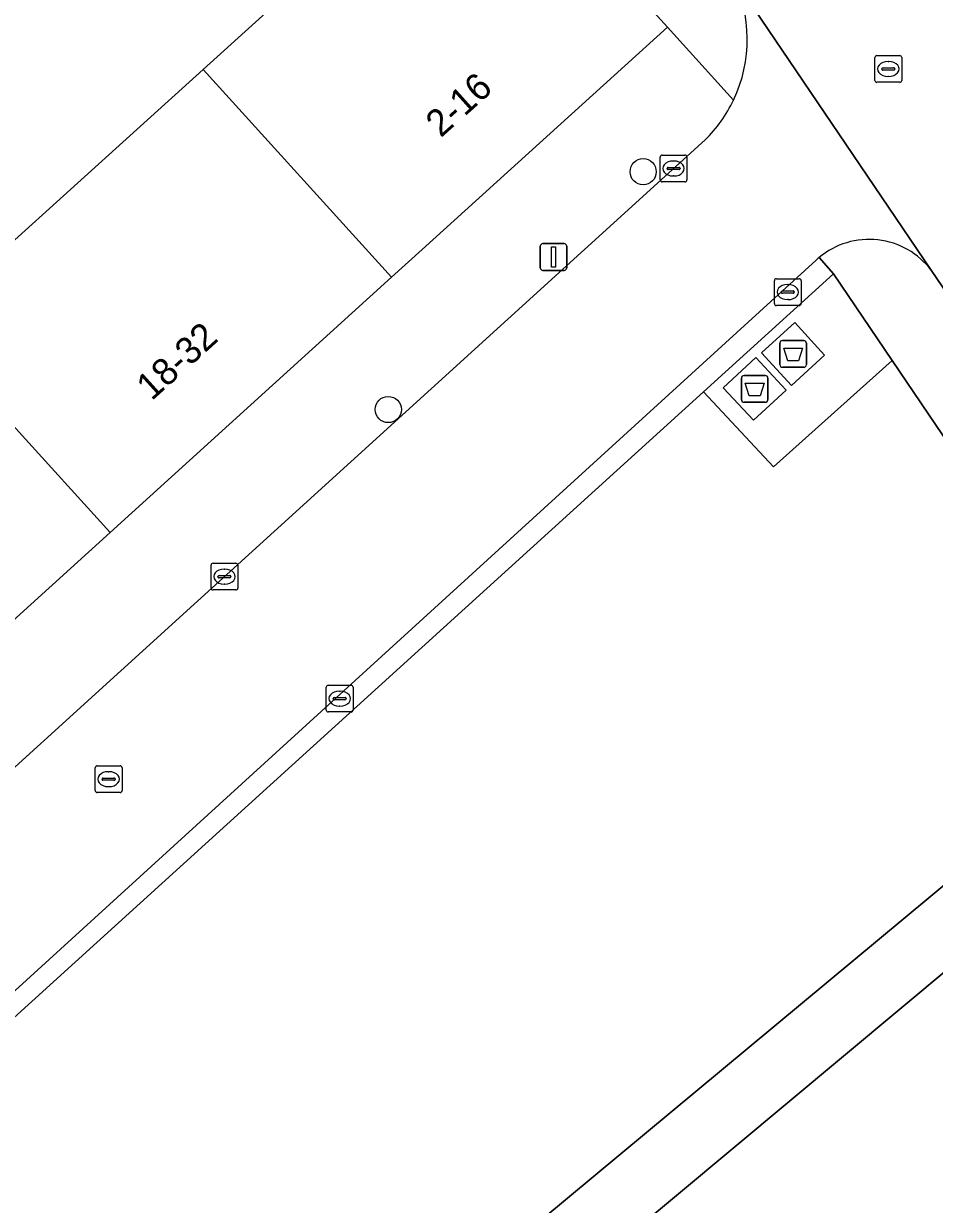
# Model space of a CAD drawing. Extents: x 159888 to 160761, y 384031 to 384750.
# Drawn here: x 160419.72 to 160453.75, y 384214.34 to 384258.44 of the extents above; entities that cross this region are included whole.
import ezdxf

# ---------------------------------------------------------------- set-up
doc = ezdxf.new("R2010")
doc.units = 0
for name, color, linetype in [('IMGEO_Afval_apart_plaats', 7, 'Continuous'), ('IMGEO_Boom', 7, 'Continuous'), ('IMGEO_Erf', 7, 'Continuous'), ('IMGEO_Groenvoorziening', 7, 'Continuous'), ('IMGEO_Kolk', 7, 'Continuous'), ('IMGEO_Lichtmast', 7, 'Continuous'), ('IMGEO_Pand', 7, 'Continuous'), ('IMGEO_Pand_nummerreeks', 7, 'Continuous'), ('IMGEO_Rijbaan_lokaal_open', 7, 'Continuous'), ('IMGEO_Rioolput', 7, 'Continuous'), ('IMGEO_Voetpad_gesloten', 7, 'Continuous'), ('IMGEO_Voetpad_open', 7, 'Continuous')]:
    doc.layers.add(name, color=color, linetype=linetype)

msp = doc.modelspace()

# ---------------------------------------------------------------- linework, layer by layer
at = {"layer": 'IMGEO_Afval_apart_plaats'}
for p, q in [((160447.976, 384245.698), (160447.976, 384246.498)), ((160447.976, 384246.498), (160447.976, 384245.698)), ((160448.076, 384246.598), (160448.866, 384246.598)), ((160448.866, 384246.598), (160448.076, 384246.598)), ((160448.966, 384246.498), (160448.966, 384245.698)), ((160448.966, 384245.698), (160448.966, 384246.498)), ((160448.866, 384245.598), (160448.076, 384245.598)), ((160448.076, 384245.598), (160448.866, 384245.598)), ((160446.54, 384244.392), (160446.54, 384245.192)), ((160446.54, 384245.192), (160446.54, 384244.392)), ((160446.64, 384245.292), (160447.43, 384245.292)), ((160447.43, 384245.292), (160446.64, 384245.292)), ((160447.53, 384245.192), (160447.53, 384244.392)), ((160447.53, 384244.392), (160447.53, 384245.192)), ((160447.43, 384244.292), (160446.64, 384244.292)), ((160446.64, 384244.292), (160447.43, 384244.292))]:
    msp.add_line(p, q, dxfattribs=at)
for points in [[(160448.119, 384246.312), (160448.823, 384246.312), (160448.674, 384245.842), (160448.268, 384245.842), (160448.119, 384246.312)], [(160446.683, 384245.006), (160447.387, 384245.006), (160447.238, 384244.536), (160446.832, 384244.536), (160446.683, 384245.006)]]:
    msp.add_lwpolyline(points, dxfattribs=at)
for centre, start, end in [((160448.076, 384246.498), 90, 180), ((160448.076, 384246.498), 90, 180), ((160448.866, 384246.498), 0, 90), ((160448.866, 384246.498), 360, 90), ((160448.076, 384245.698), 180, 270), ((160448.076, 384245.698), 180, 270), ((160448.866, 384245.698), 270, 0), ((160448.866, 384245.698), 270, 0), ((160446.64, 384245.192), 90, 180), ((160446.64, 384245.192), 90, 180), ((160447.43, 384245.192), 0, 90), ((160447.43, 384245.192), 360, 90), ((160446.64, 384244.392), 180, 270), ((160446.64, 384244.392), 180, 270), ((160447.43, 384244.392), 270, 0), ((160447.43, 384244.392), 270, 0)]:
    msp.add_arc(centre, 0.1, start, end, dxfattribs=at)
at = {"layer": 'IMGEO_Boom'}
for centre in [(160442.868, 384252.904), (160433.344, 384244.022)]:
    msp.add_circle(centre, 0.489, dxfattribs=at)
at = {"layer": 'IMGEO_Erf'}
for points in [[(160415.894, 384247.195), (160418.994, 384250), (160426.423, 384256.722), (160436.74, 384266.058), (160437.684, 384267.073), (160432.866, 384274.257), (160406.309, 384250), (160394.332, 384239.06), (160393.278, 384238.132), (160385.071, 384230.903), (160377.553, 384231.423), (160373.824, 384235.664), (160374.226, 384244.326), (160369.777, 384244.623), (160364.144, 384239.222), (160389.244, 384208.933), (160391.374, 384210.83), (160384.306, 384218.612), (160394.835, 384228.14), (160405.365, 384237.667)], [(160445.745, 384203.546), (160456.575, 384212.575), (160467.421, 384221.617), (160468.175, 384222.224), (160462.762, 384230.216), (160419.38, 384194.033), (160413.229, 384188.902), (160401.999, 384190.089), (160403.03, 384199.875), (160396.267, 384200.587), (160392.322, 384197.688), (160392.679, 384197.264), (160418.154, 384167.028), (160419.883, 384168.51), (160413.255, 384176.46), (160424.085, 384185.489), (160434.915, 384194.518)]]:
    msp.add_lwpolyline(points, close=True, dxfattribs=at)
at = {"layer": 'IMGEO_Groenvoorziening'}
msp.add_lwpolyline([(160419.212, 384221.179), (160417.064, 384200.601), (160419.671, 384197.644), (160461.362, 384232.282), (160452.167, 384245.857), (160447.736, 384241.886), (160445.123, 384244.678)], close=True, dxfattribs=at)
at = {"layer": 'IMGEO_Kolk'}
for p, q in [((160443.502, 384252.598), (160443.502, 384253.45)), ((160443.577, 384253.524), (160444.429, 384253.524)), ((160444.503, 384253.45), (160444.503, 384252.598)), ((160443.761, 384253.018), (160443.761, 384253.03)), ((160443.804, 384253.067), (160444.202, 384253.067)), ((160443.99, 384253.304), (160444.015, 384253.304)), ((160444.245, 384253.03), (160444.245, 384253.018)), ((160444.199, 384252.981), (160443.801, 384252.981)), ((160444.013, 384252.744), (160443.988, 384252.744)), ((160444.429, 384252.524), (160443.577, 384252.524)), ((160447.771, 384247.981), (160447.771, 384248.833)), ((160447.846, 384248.907), (160448.698, 384248.907)), ((160448.259, 384248.687), (160448.284, 384248.687)), ((160448.772, 384248.833), (160448.772, 384247.981)), ((160448.03, 384248.401), (160448.03, 384248.413)), ((160448.468, 384248.364), (160448.07, 384248.364)), ((160448.073, 384248.45), (160448.471, 384248.45)), ((160448.514, 384248.413), (160448.514, 384248.401)), ((160448.698, 384247.907), (160447.846, 384247.907)), ((160448.282, 384248.127), (160448.257, 384248.127)), ((160426.72, 384237.356), (160426.72, 384238.208)), ((160426.795, 384238.282), (160427.647, 384238.282)), ((160427.208, 384238.062), (160427.233, 384238.062)), ((160427.721, 384238.208), (160427.721, 384237.356)), ((160426.979, 384237.776), (160426.979, 384237.788)), ((160427.417, 384237.739), (160427.019, 384237.739)), ((160427.022, 384237.825), (160427.42, 384237.825)), ((160427.463, 384237.788), (160427.463, 384237.776)), ((160427.647, 384237.282), (160426.795, 384237.282)), ((160427.231, 384237.502), (160427.206, 384237.502)), ((160431.027, 384232.799), (160431.027, 384233.651)), ((160431.102, 384233.725), (160431.954, 384233.725)), ((160432.028, 384233.651), (160432.028, 384232.799)), ((160431.286, 384233.219), (160431.286, 384233.231)), ((160431.724, 384233.182), (160431.326, 384233.182)), ((160431.329, 384233.268), (160431.727, 384233.268)), ((160431.515, 384233.505), (160431.54, 384233.505)), ((160431.77, 384233.231), (160431.77, 384233.219)), ((160431.954, 384232.725), (160431.102, 384232.725)), ((160431.538, 384232.945), (160431.513, 384232.945))]:
    msp.add_line(p, q, dxfattribs=at)
for points in [[(160443.502, 384252.598), (160443.502, 384253.45)], [(160443.577, 384253.524), (160444.429, 384253.524)], [(160444.503, 384253.45), (160444.503, 384252.598)], [(160444.429, 384252.524), (160443.577, 384252.524)], [(160447.771, 384247.981), (160447.771, 384248.833)], [(160447.846, 384248.907), (160448.698, 384248.907)], [(160448.772, 384248.833), (160448.772, 384247.981)], [(160448.698, 384247.907), (160447.846, 384247.907)], [(160426.72, 384237.356), (160426.72, 384238.208)], [(160426.795, 384238.282), (160427.647, 384238.282)], [(160427.721, 384238.208), (160427.721, 384237.356)], [(160427.647, 384237.282), (160426.795, 384237.282)], [(160431.027, 384232.799), (160431.027, 384233.651)], [(160431.102, 384233.725), (160431.954, 384233.725)], [(160432.028, 384233.651), (160432.028, 384232.799)], [(160431.954, 384232.725), (160431.102, 384232.725)]]:
    msp.add_lwpolyline(points, dxfattribs=at)
for centre, radius, start, end in [((160443.579, 384253.448), 0.0765, 91.552, 178.448), ((160443.579, 384253.448), 0.0765, 91.552, 178.448), ((160444.427, 384253.448), 0.0765, 1.552, 88.448), ((160444.427, 384253.448), 0.0765, 1.552, 88.448), ((160443.801, 384253.027), 0.0403, 85.8775, 175.7526), ((160443.798, 384253.017), 0.0366, 178.938, 274.7102), ((160444.202, 384253.024), 0.043, 264.8664, 352.4533), ((160444.206, 384253.029), 0.0386, 1.7309, 96.639), ((160443.579, 384252.6), 0.0765, 181.552, 268.448), ((160443.579, 384252.6), 0.0765, 181.552, 268.448), ((160444.427, 384252.6), 0.0765, 271.552, 358.448), ((160444.427, 384252.6), 0.0765, 271.552, 358.448), ((160447.848, 384248.831), 0.0765, 91.552, 178.448), ((160447.848, 384248.831), 0.0765, 91.552, 178.448), ((160448.696, 384248.831), 0.0765, 1.552, 88.448), ((160448.696, 384248.831), 0.0765, 1.552, 88.448), ((160448.07, 384248.41), 0.0403, 85.8775, 175.7526), ((160448.067, 384248.4), 0.0366, 178.938, 274.7102), ((160448.471, 384248.407), 0.043, 264.8664, 352.4533), ((160448.475, 384248.412), 0.0386, 1.7309, 96.639), ((160447.848, 384247.983), 0.0765, 181.552, 268.448), ((160447.848, 384247.983), 0.0765, 181.552, 268.448), ((160448.696, 384247.983), 0.0765, 271.552, 358.448), ((160448.696, 384247.983), 0.0765, 271.552, 358.448), ((160426.797, 384238.206), 0.0765, 91.552, 178.448), ((160426.797, 384238.206), 0.0765, 91.552, 178.448), ((160427.645, 384238.206), 0.0765, 1.552, 88.448), ((160427.645, 384238.206), 0.0765, 1.552, 88.448), ((160427.019, 384237.785), 0.0403, 85.8775, 175.7526), ((160427.016, 384237.775), 0.0366, 178.938, 274.7102), ((160427.42, 384237.782), 0.043, 264.8664, 352.4533), ((160427.424, 384237.787), 0.0386, 1.7309, 96.639), ((160426.797, 384237.358), 0.0765, 181.552, 268.448), ((160426.797, 384237.358), 0.0765, 181.552, 268.448), ((160427.645, 384237.358), 0.0765, 271.552, 358.448), ((160427.645, 384237.358), 0.0765, 271.552, 358.448), ((160431.104, 384233.649), 0.0765, 91.552, 178.448), ((160431.104, 384233.649), 0.0765, 91.552, 178.448), ((160431.952, 384233.649), 0.0765, 1.552, 88.448), ((160431.952, 384233.649), 0.0765, 1.552, 88.448), ((160431.326, 384233.228), 0.0403, 85.8775, 175.7526), ((160431.323, 384233.218), 0.0366, 178.938, 274.7102), ((160431.727, 384233.225), 0.043, 264.8664, 352.4533), ((160431.731, 384233.23), 0.0386, 1.7309, 96.639), ((160431.104, 384232.801), 0.0765, 181.552, 268.448), ((160431.104, 384232.801), 0.0765, 181.552, 268.448), ((160431.952, 384232.801), 0.0765, 271.552, 358.448), ((160431.952, 384232.801), 0.0765, 271.552, 358.448)]:
    msp.add_arc(centre, radius, start, end, dxfattribs=at)
for centre, major_axis, ratio, start_param, end_param in [((160443.989, 384253.024), (-0.387, 0.002), 0.722429, 4.712389, 7.853982), ((160444.014, 384253.024), (-0.39, 0.002), 0.717154, 1.570796, 4.712389), ((160448.258, 384248.407), (-0.387, 0.002), 0.722429, 4.712389, 7.853982), ((160448.283, 384248.407), (-0.39, 0.002), 0.717154, 1.570796, 4.712389), ((160427.207, 384237.782), (-0.387, 0.002), 0.722429, 4.712389, 7.853982), ((160427.232, 384237.782), (-0.39, 0.002), 0.717154, 1.570796, 4.712389), ((160431.514, 384233.225), (-0.387, 0.002), 0.722429, 4.712389, 7.853982), ((160431.539, 384233.225), (-0.39, 0.002), 0.717154, 1.570796, 4.712389)]:
    msp.add_ellipse(centre, major_axis=major_axis, ratio=ratio, start_param=start_param, end_param=end_param, dxfattribs=at)
at = {"layer": 'IMGEO_Lichtmast'}
for p, q in [((160439.022, 384249.318), (160439.022, 384250.118)), ((160439.022, 384250.118), (160439.022, 384249.318)), ((160439.122, 384250.218), (160439.912, 384250.218)), ((160439.912, 384250.218), (160439.122, 384250.218)), ((160440.012, 384250.118), (160440.012, 384249.318)), ((160440.012, 384249.318), (160440.012, 384250.118)), ((160439.912, 384249.218), (160439.122, 384249.218)), ((160439.122, 384249.218), (160439.912, 384249.218))]:
    msp.add_line(p, q, dxfattribs=at)
msp.add_lwpolyline([(160439.442, 384250.093), (160439.592, 384250.093), (160439.592, 384249.343), (160439.442, 384249.343), (160439.442, 384250.093)], dxfattribs=at)
for centre, start, end in [((160439.122, 384250.118), 90, 180), ((160439.122, 384250.118), 90, 180), ((160439.912, 384250.118), 0, 90), ((160439.912, 384250.118), 360, 90), ((160439.122, 384249.318), 180, 270), ((160439.122, 384249.318), 180, 270), ((160439.912, 384249.318), 270, 0), ((160439.912, 384249.318), 270, 0)]:
    msp.add_arc(centre, 0.1, start, end, dxfattribs=at)
at = {"layer": 'IMGEO_Pand'}
for points in [[(160426.423, 384256.722), (160433.468, 384248.966), (160434.61, 384250), (160443.774, 384258.302), (160436.74, 384266.058)], [(160426.423, 384256.722), (160418.994, 384250), (160415.894, 384247.195), (160422.945, 384239.432), (160433.468, 384248.966)], [(160415.894, 384247.195), (160405.365, 384237.667), (160412.421, 384229.898), (160422.945, 384239.432)]]:
    msp.add_lwpolyline(points, close=True, dxfattribs=at)
at = {"layer": 'IMGEO_Rijbaan_lokaal_open'}
for points in [[(160453.631, 384249.222), (160446.201, 384260.194)], [(160446.201, 384260.194), (160453.631, 384249.222), (160476.697, 384215.312), (160476.89, 384215.003), (160477.055, 384214.679), (160477.189, 384214.34), (160477.293, 384213.991), (160477.366, 384213.634), (160477.37, 384213.596), (160483.05, 384204.786), (160483.161, 384204.745), (160483.396, 384204.636), (160483.62, 384204.507), (160483.831, 384204.358), (160484.029, 384204.191), (160484.21, 384204.007), (160484.375, 384203.808), (160497.404, 384184.565)], [(160445.18, 384254.092), (160440.675, 384250), (160400.149, 384213.193), (160395.244, 384208.801), (160392.259, 384206.298), (160388.92, 384203.637), (160388.797, 384203.549), (160386.395, 384201.834), (160376.559, 384195.084), (160373.781, 384193.161)], [(160372.412, 384190.774), (160371.855, 384190.41), (160374.745, 384186.163), (160375.465, 384186.68), (160380.904, 384190.464), (160389.416, 384196.161), (160392.025, 384198.09), (160395.382, 384200.689), (160397.932, 384202.765), (160449.329, 384249.596)]]:
    msp.add_lwpolyline(points, dxfattribs=at)
for centre, radius, start, end in [((160441.517, 384257.842), 5.241, 334.4248, 26.6677), ((160441.513, 384257.843), 5.246, 314.3501, 334.4289), ((160451.311, 384247.465), 2.911, 37.1415, 129.917), ((160451.239, 384247.555), 2.796, 129.9788, 133.1008)]:
    msp.add_arc(centre, radius, start, end, dxfattribs=at)
at = {"layer": 'IMGEO_Rioolput'}
for p, q in [((160451.529, 384256.316), (160451.529, 384257.168)), ((160451.604, 384257.242), (160452.456, 384257.242)), ((160452.017, 384257.022), (160452.042, 384257.022)), ((160452.53, 384257.168), (160452.53, 384256.316)), ((160451.788, 384256.736), (160451.788, 384256.748)), ((160452.226, 384256.699), (160451.828, 384256.699)), ((160451.831, 384256.785), (160452.229, 384256.785)), ((160452.272, 384256.748), (160452.272, 384256.736)), ((160452.456, 384256.242), (160451.604, 384256.242)), ((160452.04, 384256.462), (160452.015, 384256.462)), ((160422.393, 384229.79), (160422.393, 384230.642)), ((160422.468, 384230.716), (160423.32, 384230.716)), ((160423.394, 384230.642), (160423.394, 384229.79)), ((160422.652, 384230.21), (160422.652, 384230.222)), ((160423.09, 384230.173), (160422.692, 384230.173)), ((160422.695, 384230.259), (160423.093, 384230.259)), ((160422.881, 384230.496), (160422.906, 384230.496)), ((160423.136, 384230.222), (160423.136, 384230.21)), ((160423.32, 384229.716), (160422.468, 384229.716)), ((160422.904, 384229.936), (160422.879, 384229.936))]:
    msp.add_line(p, q, dxfattribs=at)
for points in [[(160451.529, 384256.316), (160451.529, 384257.168)], [(160451.604, 384257.242), (160452.456, 384257.242)], [(160452.53, 384257.168), (160452.53, 384256.316)], [(160452.456, 384256.242), (160451.604, 384256.242)], [(160422.393, 384229.79), (160422.393, 384230.642)], [(160422.468, 384230.716), (160423.32, 384230.716)], [(160423.394, 384230.642), (160423.394, 384229.79)], [(160423.32, 384229.716), (160422.468, 384229.716)]]:
    msp.add_lwpolyline(points, dxfattribs=at)
for centre, radius, start, end in [((160451.606, 384257.166), 0.0765, 91.552, 178.448), ((160451.606, 384257.166), 0.0765, 91.552, 178.448), ((160452.454, 384257.166), 0.0765, 1.552, 88.448), ((160452.454, 384257.166), 0.0765, 1.552, 88.448), ((160451.828, 384256.745), 0.0403, 85.8775, 175.7526), ((160451.825, 384256.735), 0.0366, 178.938, 274.7102), ((160452.229, 384256.742), 0.043, 264.8664, 352.4533), ((160452.233, 384256.747), 0.0386, 1.7309, 96.639), ((160451.606, 384256.318), 0.0765, 181.552, 268.448), ((160451.606, 384256.318), 0.0765, 181.552, 268.448), ((160452.454, 384256.318), 0.0765, 271.552, 358.448), ((160452.454, 384256.318), 0.0765, 271.552, 358.448), ((160422.47, 384230.64), 0.0765, 91.552, 178.448), ((160422.47, 384230.64), 0.0765, 91.552, 178.448), ((160423.318, 384230.64), 0.0765, 1.552, 88.448), ((160423.318, 384230.64), 0.0765, 1.552, 88.448), ((160422.692, 384230.219), 0.0403, 85.8775, 175.7526), ((160422.689, 384230.209), 0.0366, 178.938, 274.7102), ((160423.093, 384230.216), 0.043, 264.8664, 352.4533), ((160423.097, 384230.221), 0.0386, 1.7309, 96.639), ((160422.47, 384229.792), 0.0765, 181.552, 268.448), ((160422.47, 384229.792), 0.0765, 181.552, 268.448), ((160423.318, 384229.792), 0.0765, 271.552, 358.448), ((160423.318, 384229.792), 0.0765, 271.552, 358.448)]:
    msp.add_arc(centre, radius, start, end, dxfattribs=at)
for centre, major_axis, ratio, start_param, end_param in [((160452.016, 384256.742), (-0.387, 0.002), 0.722429, 4.712389, 7.853982), ((160452.041, 384256.742), (-0.39, 0.002), 0.717154, 1.570796, 4.712389), ((160422.88, 384230.216), (-0.387, 0.002), 0.722429, 4.712389, 7.853982), ((160422.905, 384230.216), (-0.39, 0.002), 0.717154, 1.570796, 4.712389)]:
    msp.add_ellipse(centre, major_axis=major_axis, ratio=ratio, start_param=start_param, end_param=end_param, dxfattribs=at)
at = {"layer": 'IMGEO_Voetpad_gesloten'}
for points in [[(160448.537, 384247.272), (160447.296, 384246.142), (160448.405, 384244.924), (160449.646, 384246.054)], [(160447.079, 384245.964), (160445.863, 384244.835), (160446.991, 384243.62), (160448.207, 384244.749)]]:
    msp.add_lwpolyline(points, close=True, dxfattribs=at)
at = {"layer": 'IMGEO_Voetpad_open'}
for points in [[(160419.968, 384293.492), (160431.422, 384276.411), (160432.866, 384274.257), (160437.684, 384267.073), (160436.74, 384266.058), (160443.774, 384258.302), (160446.245, 384255.579)], [(160446.245, 384255.579), (160443.774, 384258.302), (160434.61, 384250), (160433.468, 384248.966), (160422.945, 384239.432), (160412.421, 384229.898), (160401.898, 384220.364), (160391.374, 384210.83), (160389.244, 384208.933), (160386.728, 384206.983), (160368.445, 384194.271), (160371.855, 384190.41), (160372.412, 384190.774)], [(160440.675, 384250), (160445.18, 384254.092)], [(160373.781, 384193.161), (160376.559, 384195.084), (160386.395, 384201.834), (160388.797, 384203.549), (160388.151, 384204.364), (160391.613, 384207.113), (160392.259, 384206.298), (160395.244, 384208.801), (160400.149, 384213.193), (160440.675, 384250)], [(160449.329, 384249.596), (160397.932, 384202.765), (160395.382, 384200.689), (160392.025, 384198.09), (160392.322, 384197.688), (160396.267, 384200.587)], [(160396.267, 384200.587), (160399.146, 384202.981), (160416.564, 384218.778), (160419.212, 384221.179), (160445.123, 384244.678), (160449.981, 384249.084), (160449.443, 384249.697)], [(160449.443, 384249.697), (160449.981, 384249.084), (160452.167, 384245.857), (160461.362, 384232.282), (160462.762, 384230.216), (160468.175, 384222.224), (160467.421, 384221.617), (160474.049, 384213.667), (160476.617, 384210.587), (160476.792, 384210.839), (160476.972, 384211.156)], [(160476.89, 384215.003), (160476.697, 384215.312), (160453.631, 384249.222)]]:
    msp.add_lwpolyline(points, dxfattribs=at)
for points in [[(160445.123, 384244.678), (160447.736, 384241.886), (160452.167, 384245.857), (160449.981, 384249.084)], [(160448.405, 384244.924), (160447.296, 384246.142), (160448.537, 384247.272), (160449.646, 384246.054)], [(160446.991, 384243.62), (160445.863, 384244.835), (160447.079, 384245.964), (160448.207, 384244.749)], [(160419.212, 384221.179), (160416.564, 384218.778), (160414.45, 384201.178), (160399.146, 384202.981), (160396.267, 384200.587), (160403.03, 384199.875), (160415.475, 384198.563), (160419.38, 384194.033), (160462.762, 384230.216), (160461.362, 384232.282), (160419.671, 384197.644), (160417.064, 384200.601)]]:
    msp.add_lwpolyline(points, close=True, dxfattribs=at)
for centre, radius, start, end in [((160441.517, 384257.842), 5.241, 334.4248, 26.6677), ((160441.513, 384257.843), 5.246, 314.3501, 334.4289), ((160451.311, 384247.465), 2.911, 37.1415, 129.917), ((160451.239, 384247.555), 2.796, 129.9788, 133.1008)]:
    msp.add_arc(centre, radius, start, end, dxfattribs=at)

# ---------------------------------------------------------------- texts
at = {"layer": 'IMGEO_Pand_nummerreeks'}
for s, rotation, p in [('2-16', 41.9377, (160435.306, 384254.152)), ('18-32', 42.1203, (160424.5, 384244.325))]:
    msp.add_text(s, height=1, rotation=rotation, dxfattribs=at).set_placement(p)

doc.saveas('drawing.dxf')
